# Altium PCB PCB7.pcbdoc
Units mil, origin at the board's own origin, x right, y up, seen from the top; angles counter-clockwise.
Board outline 2900 x 4300 mil, 2 copper layers (Top Layer, Bottom Layer); 31 components, 28 nets, 92 pads, 27 vias.
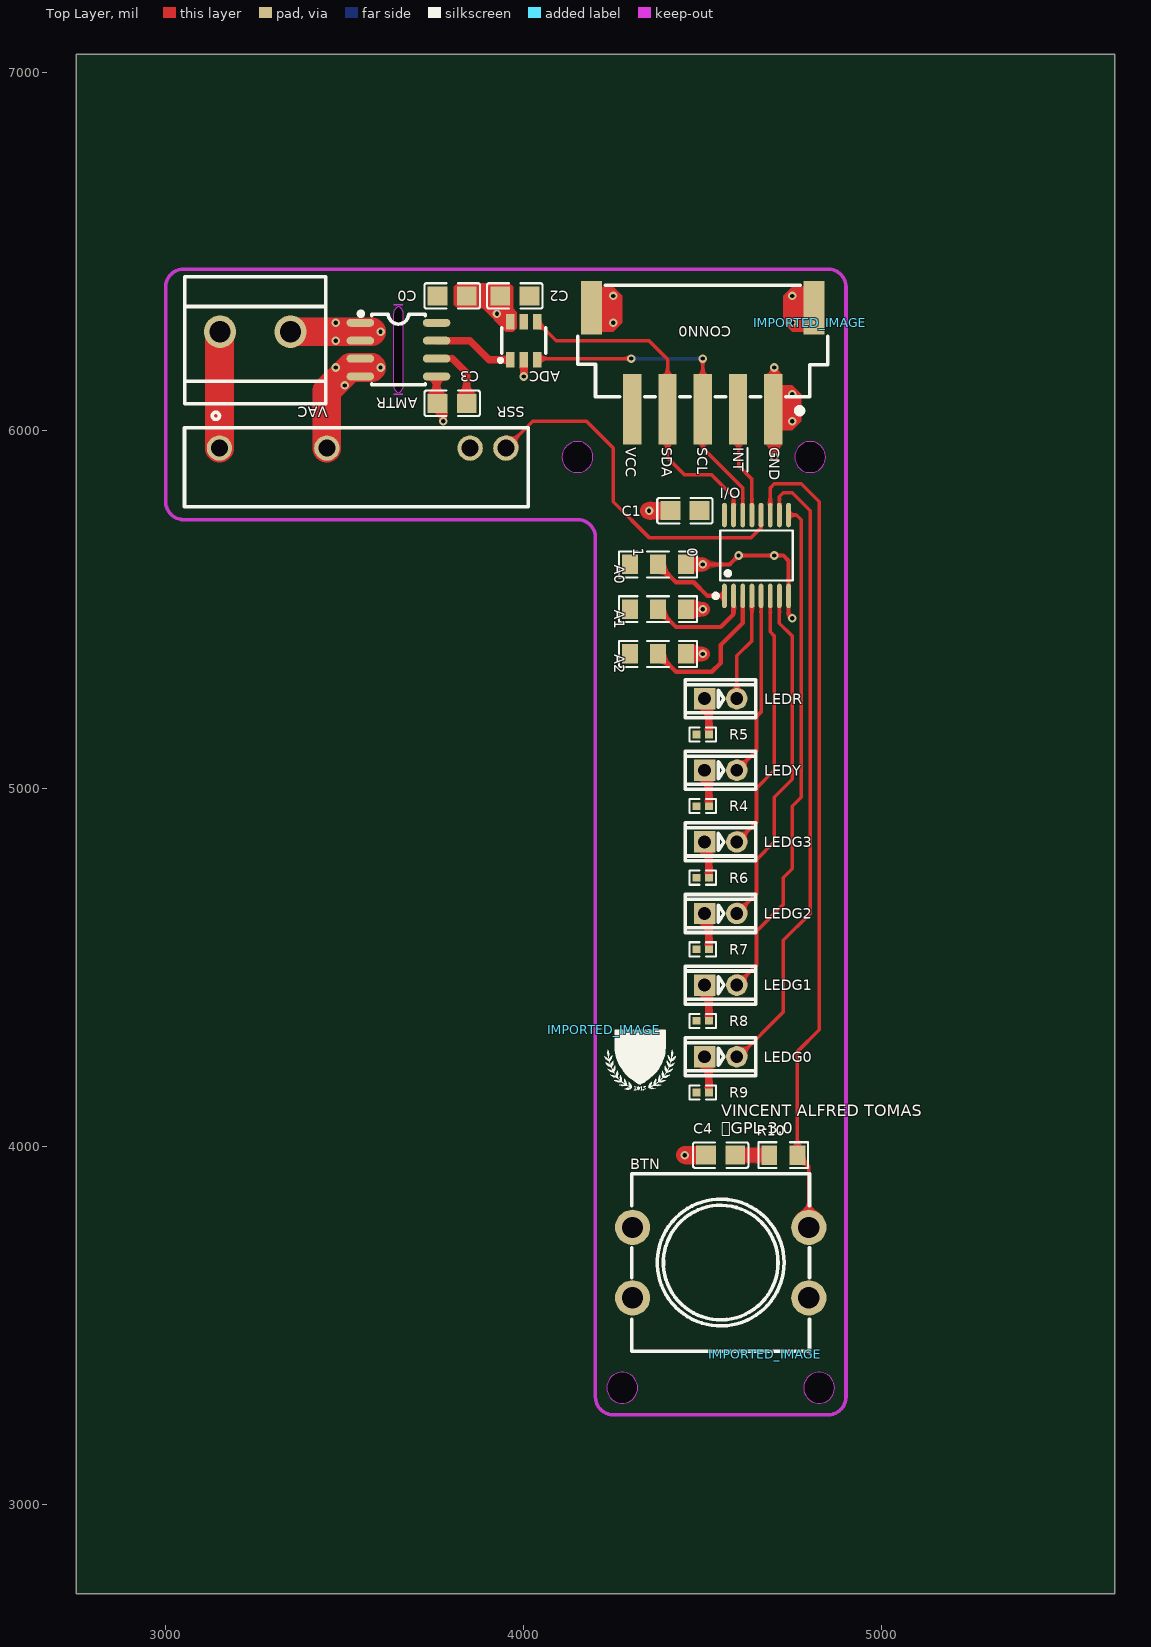
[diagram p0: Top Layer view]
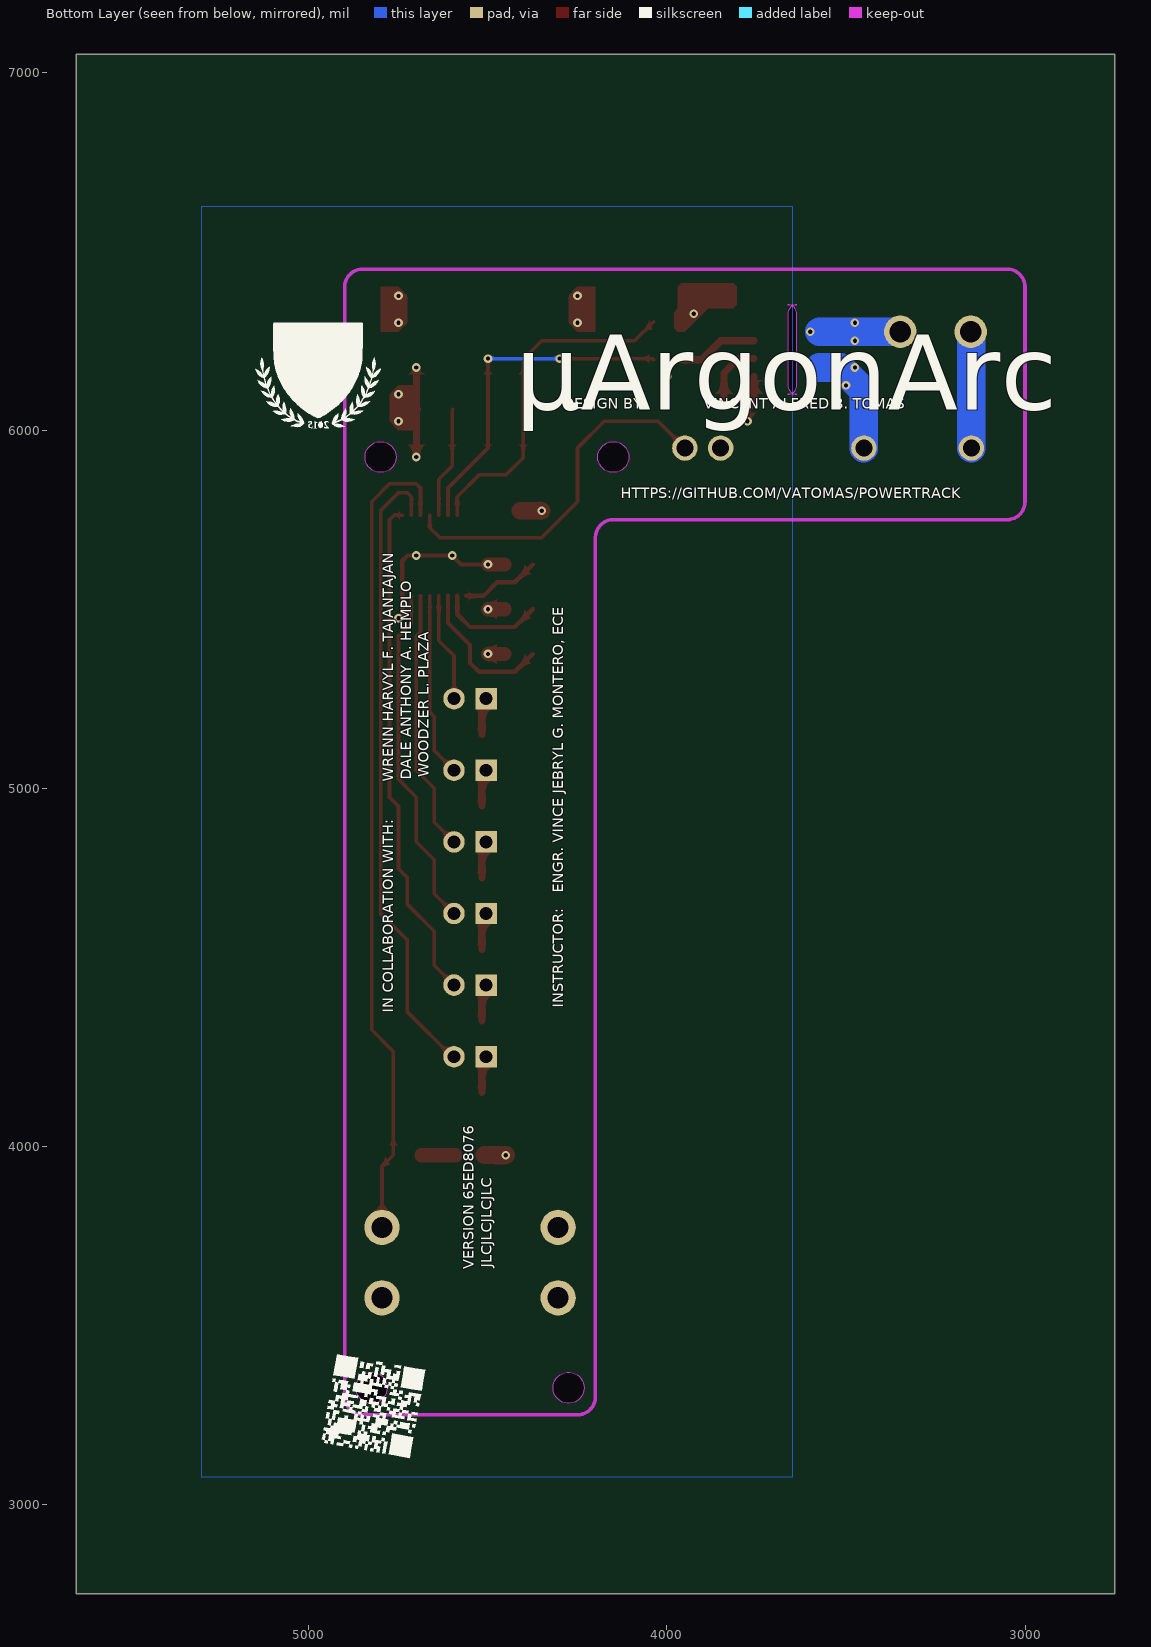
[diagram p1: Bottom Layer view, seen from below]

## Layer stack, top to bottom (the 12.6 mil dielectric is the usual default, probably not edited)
Top Layer: signal copper (thickness not stored)
Dielectric: dielectric 12.6, FR-4, Dk 4.8
Bottom Layer: signal copper (thickness not stored)

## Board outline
5650,2750 2750,2750 2750,7050 5650,7050
cut-out: 4843.31,5925 ccw(c4800,5925) 4756.69,5925 ccw(c4800,5925)
cut-out: 4193.31,5925 ccw(c4150,5925) 4106.69,5925 ccw(c4150,5925)
cut-out: 4868.31,3325 ccw(c4825,3325) 4781.69,3325 ccw(c4825,3325)
cut-out: 4318.31,3325 ccw(c4275,3325) 4231.69,3325 ccw(c4275,3325)
cut-out: 3662.5,6350 3637.5,6350 cw(c3637.5,6325) 3662.5,6325 3662.5,6125 cw(c3637.5,6125) 3637.5,6100 3662.5,6100 cw(c3662.5,6125) 3637.5,6125 3637.5,6325 cw(c3662.5,6325)

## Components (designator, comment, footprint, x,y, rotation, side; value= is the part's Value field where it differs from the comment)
A0 "Solder Switch" "Solder Switch" 4375,5625 r0 top
A1 "Solder Switch" "Solder Switch" 4375,5500 r0 top
A2 "Solder Switch" "Solder Switch" 4375,5375 r0 top
ADC "ADS1110A0IDBVR" SOT-23-6_L2.9-W1.6-P0.95-LS2.8-BR 4000,6250 r270 top
AMTR "ACS712ELCTR-05B-T" SOIC-8_L5.0-W4.0-P1.27-LS6.0-BL 3650,6225 r270 top
BTN "TS-1003-10026" SW-TH_4P-L12.0-W12.0-P5.00-LS12.5 4550,3675 r0 top
C0 "C2012X7T2E104KT000N" C0805 3800,6375 r180 top
C1 "C2012X7T2E104KT000N" C0805 4450,5775 r0 top
C2 "0805B181K500NT" C0805 3800,6075 r0 top
C3 "C2012X7T2E104KT000N" C0805 3975,6375 r0 top
C4 "0805B105K500NT_C215803" C0805 4550,3975 r180 top
CONN0 "XH-5PWB" CONN-SMD_5P-P2.50_DEALON_XH-5PWB 4500,6200 r180 top
I/O "TCA9534APWR" TSSOP-16_L5.0-W4.4-P0.65-LS6.4-BL 4650,5650 r0 top
IMPORTED_IMAGE "IMPORTED_IMAGE" IMPORTED_IMAGE 4225,4325 r0 top
IMPORTED_IMAGE "IMPORTED_IMAGE" IMPORTED_IMAGE 4675,3419.01 r0 top
IMPORTED_IMAGE "IMPORTED_IMAGE" IMPORTED_IMAGE 4800,6300 r0 top
LEDG0 "TZ-L2-25FYBYG2YCJ140-001" LED-TH_L5.0-W2.7-FD 4550,4250 r0 top
LEDG1 "TZ-L2-25FYBYG2YCJ140-001" LED-TH_L5.0-W2.7-FD 4550,4450 r0 top
LEDG2 "TZ-L2-25FYBYG2YCJ140-001" LED-TH_L5.0-W2.7-FD 4550,4650 r0 top
LEDG3 "TZ-L2-25FYBYG2YCJ140-001" LED-TH_L5.0-W2.7-FD 4550,4850 r0 top
LEDR "TJ-L257FGHRMFCSFLC2R-A5" LED-TH_L5.0-W2.7-FD 4550,5250 r0 top
LEDY "TZ-L2-25FYBY2YCJ150-001" LED-TH_L5.0-W2.7-FD 4550,5050 r0 top
R4 "CR0402FF2211G" R0402 4500,4950 r180 top
R5 "RTT023091FTH" R0402 4500,5150 r180 top
R6 "0402WGD3300TCE" R0402 4500,4750 r180 top
R7 "0402WGD3300TCE" R0402 4500,4550 r180 top
R8 "0402WGD3300TCE" R0402 4500,4350 r180 top
R9 "0402WGD3300TCE" R0402 4500,4150 r180 top
R10 "Res_0805" R0805 4725,3975 r0 top
SSR "G3MB-202PL" RELAY-TH_G3MB-202PL 3550,5950 r180 top
VAC "XY126V-5.0-2P" CONN-TH_XY126V-5.0-2P 3250,6275 r0 top

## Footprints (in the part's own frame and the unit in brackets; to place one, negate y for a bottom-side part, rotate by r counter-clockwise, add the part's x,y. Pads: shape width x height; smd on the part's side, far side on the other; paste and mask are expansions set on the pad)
C0805 [mm]
  rect 1.41x1.35 smd: 1(-1.03,0) 2(1.03,0)
  silkscreen extent -1.96,-0.9 1.96,0.9
CONN-SMD_5P-P2.50_DEALON_XH-5PWB [mm]
  rect 1.3x5 smd: 1(-5,3.6) 2(-2.5,3.6) 3(0,3.6) 4(2.5,3.6) 5(5,3.6)
  rect 1.5x3.8 smd: 6(-7.9,-3.6) 7(7.9,-3.6)
  silkscreen extent -8.86,-5.2 8.86,3.9
CONN-TH_XY126V-5.0-2P [mm]
  round 2.3 hole 1.5: 1(-2.5,0) 2(2.5,0)
  silkscreen extent -5,-5.1 5,3.9
IMPORTED_IMAGE [mil]
  silkscreen extent 0,-169 200,0
LED-TH_L5.0-W2.7-FD [mil]
  rect 60x60 hole 36: 1(-44.88,0)
  round 60 hole 36: 2(44.88,0)
  silkscreen extent -98,-53 98,53
R0402 [mm]
  rect 0.566x0.54 smd: 1(-0.433,0) 2(0.433,0)
  silkscreen extent -0.94,-0.5 0.94,0.5
R0805 [mm]
  rect 1.133x1.377 smd: 1(-1,0) 2(1,0)
  silkscreen extent -1.76,-0.92 1.76,0.92
RELAY-TH_G3MB-202PL [mm]
  round 1.8 hole 1.2: 1(10.16,0) 2(2.54,0) 3(-7.62,0) 4(-10.16,0)
  silkscreen extent -11.74,-2.54 12.64,4.15
SOIC-8_L5.0-W4.0-P1.27-LS6.0-BL [mil]
  oval 22.38x76.78 smd: 1(-75,-106.5) 2(-25,-106.5) 3(25,-106.5) 4(75,-106.5) 5(75,106.5) 6(25,106.5) 7(-25,106.5) 8(-75,106.5)
  silkscreen extent -106,-111 98,75
"Solder Switch" [mm]
  rect 1.133x1.377 smd: 1(-2,0) 2(0,0) 3(2,0)
  silkscreen extent -2.76,-0.92 2.76,0.92
SOT-23-6_L2.9-W1.6-P0.95-LS2.8-BR [mm]
  rect 1.1x0.6 smd: 1(1.35,-0.95) 2(1.35,0) 3(1.35,0.95) 4(-1.35,0.95) 5(-1.35,0) 6(-1.35,-0.95)
  silkscreen extent -0.9,-1.78 1.52,1.55
SW-TH_4P-L12.0-W12.0-P5.00-LS12.5 [mm]
  round 2.5 hole 1.5: 1(-6.25,2.5) 2(6.25,2.5) 3(-6.25,-2.5) 4(6.25,-2.5)
  silkscreen extent -6.3,-6.3 6.3,6.3
TSSOP-16_L5.0-W4.4-P0.65-LS6.4-BL [mil]
  oval 13.5x68.17 smd: 1(-89.57,-112.82) 2(-63.98,-112.82) 3(-38.39,-112.82) 4(-12.79,-112.82) 5(12.8,-112.82) 6(38.39,-112.82) 7(63.98,-112.82) 8(89.57,-112.82) 9(89.57,112.82) 10(63.98,112.82) 11(38.39,112.82) 12(12.8,112.82) 13(-12.79,112.82) 14(-38.39,112.82) 15(-63.98,112.82) 16(-89.57,112.82)
  silkscreen extent -120,-119 101,70

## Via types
v1: diameter 24.02, hole 12.01, Top Layer to Bottom Layer, 27 vias

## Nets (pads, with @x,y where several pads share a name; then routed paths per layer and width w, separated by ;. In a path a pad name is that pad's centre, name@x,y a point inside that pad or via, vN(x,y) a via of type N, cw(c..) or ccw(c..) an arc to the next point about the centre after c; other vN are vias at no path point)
$1N4404: LEDR.1 R5.1 | length 104.9
  Top Layer w20: LEDR.1 4517.04,5238.08 R5.1
$1N4407: LEDY.1 R4.1 | length 104.9
  Top Layer w20: LEDY.1 4517.04,5038.08 R4.1
$1N4410: LEDG3.1 R6.1 | length 104.9
  Top Layer w20: LEDG3.1 4517.04,4838.08 R6.1
$1N4413: LEDG2.1 R7.1 | length 104.9
  Top Layer w20: LEDG2.1 4517.04,4638.08 R7.1
$1N4416: LEDG1.1 R8.1 | length 104.9
  Top Layer w20: LEDG1.1 4517.04,4438.08 R8.1
$1N4419: LEDG0.1 R9.1 | length 104.9
  Top Layer w20: LEDG0.1 4517.04,4238.08 R9.1
$1N12131: AMTR.6 C2.2 | length 185.3
  Top Layer w20: AMTR.6 3800,6200 3840.55,6159.45 C2.2
$1N12380: ADC.1 AMTR.7 | length 228.1
  Top Layer w20: AMTR.7 3850,6250 3903.15,6196.85 ADC.1
$1N13268: AMTR.3 AMTR.4 SSR.2 | length 623.8
  Top Layer w80: SSR.2 3450,6110 3515,6175 3575,6175
  Bottom Layer w80: SSR.2 3450,6110 3515,6175 3575,6175
  other v1: 3500,6125 3475,6175 3600,6175
$1N13298: SSR.1 VAC.1 | length 651.3
  Top Layer w80: SSR.1 3150,6273.43 VAC.1
  Bottom Layer w80: SSR.1 3150,6273.43 VAC.1
$1N13302: AMTR.1 AMTR.2 VAC.2 | length 453.1
  Top Layer w80: VAC.2 3575,6275
  Bottom Layer w80: VAC.2 3575,6275
  other v1: 3475,6250 3600,6275 3475,6300
+5V: A0.1 A1.1 A2.1 ADC.5 AMTR.8 C0.2 C1.2 C3.2 C4.1 CONN0.5 I/O.16 R4.2 R5.2 R6.2 R7.2 R8.2 R9.2 R10.1 SSR.3 | length 95.1
  Top Layer w40: C4.1 R10.1
A0: A0.2 I/O.1 | length 221.8
  Top Layer w12: A0.2 4425,5575 4475,5575 4512.82,5537.18 I/O.1
A1: A1.2 I/O.2 | length 297.8
  Top Layer w12: A1.2 4425,5450 4550,5450 4586.02,5486.02 I/O.2
A2: A2.2 I/O.3 | length 418.8
  Top Layer w12: A2.2 4425,5325 4525,5325 4550,5350 4550,5400 4611.61,5461.61 I/O.3
BTN: BTN.2 I/O.11 R10.2 | length 2302.5
  Top Layer w10: I/O.11 4688.39,5838.39 4700,5850 4775,5850 4825,5800 4825,4325 4764.37,4264.37 R10.2 4796.06,3943.31 BTN.2
GND: A0.3 A1.3 A2.3 ADC.2 ADC.6 AMTR.5 BTN.3 BTN.4 C0.1 C1.1 C2.1 C3.1 C4.2 CONN0.1 CONN0.6 CONN0.7 I/O.8 | length 1110.5
  Top Layer w12: v1(4500,5625) 4575,5625 v1(4600,5650) v1(4700,5650) 4725,5650 4739.57,5635.43 I/O.8 4739.57,5485.43 v1(4750,5475)
  Top Layer w20: AMTR.5 3756.5,6077.95 C2.1 3775,6059.45 v1(3775,6025) ; v1(4000,6150) ADC.2 ; v1(4700,5925) 4700,6055.12 CONN0.1 4700,6061.42 v1(4700,6175)
  Top Layer w40: A2.3 v1(4500,5375) ; A1.3 v1(4500,5500) ; A0.3 v1(4500,5625)
  Top Layer w50: v1(4350,5775) C1.1 ; v1(4450,3975) C4.2
  other v1: 4750,6025 4750,6100 4250,6300 4750,6300 3925,6325 4250,6375 4750,6375
LED0: I/O.10 LEDG0.2 | length 1775.4
  Top Layer w10: LEDG0.2 4600,4250 4725,4375 4725,4575 4800,4650 4800,5775 4750,5825 4725,5825 4713.98,5813.98 I/O.10
LED1: I/O.9 LEDG1.2 | length 1415.4
  Top Layer w10: LEDG1.2 4650,4505.12 4650,4600 4725,4675 4725,4750 4750,4775 4750,4950 4775,4975 4775,5750 4762.18,5762.82 I/O.9
LED2: I/O.7 LEDG2.2 | length 966.3
  Top Layer w10: LEDG2.2 4650,4705.12 4650,4800 4700,4850 4700,4975 4750,5025 4750,5425 4713.98,5461.02 I/O.7
LED3: I/O.6 LEDG3.2 | length 735.5
  Top Layer w10: LEDG3.2 4650,4905.12 4650,5000 4700,5050 4700,5425 4688.39,5436.61 I/O.6
LED4: I/O.5 LEDY.2 | length 515.3
  Top Layer w10: LEDY.2 4650,5105.12 4650,5200 4662.8,5212.8 I/O.5
LED5: I/O.4 LEDR.2 | length 304.7
  Top Layer w10: LEDR.2 4594.88,5369.88 4637.21,5412.21 I/O.4
SCL: ADC.3 CONN0.3 I/O.14 | length 947.3
  Top Layer w10: ADC.3 4040.55,6200 v1(4300,6200) ; v1(4500,6200) CONN0.3 4500,5950 4611.61,5838.39 I/O.14
  Bottom Layer w10: v1(4300,6200) v1(4500,6200)
SDA: ADC.4 CONN0.4 I/O.15 | length 963.5
  Top Layer w10: ADC.4 4090.55,6250 4350,6250 4401.57,6198.43 CONN0.4 4401.57,5923.43 4450,5875 4525,5875 4586.02,5813.98 I/O.15
SSR: I/O.12 SSR.4 | length 1012.9
  Top Layer w10: SSR.4 4025,6025 4175,6025 4250,5950 4250,5800 4350,5700 4635.06,5700 4662.8,5727.74 I/O.12
~INT: CONN0.2 I/O.13 | length 311.5
  Top Layer w10: CONN0.2 4600,6056.7 4600,5900 4637.21,5862.79 I/O.13
"": BTN.1

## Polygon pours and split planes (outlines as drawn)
GND on Bottom Layer (solid, remove dead copper, pour order 0): 3650,3075 5300,3075 5300,6625 3650,6625
+5V on Top Layer (solid, remove dead copper, pour order 2): 3675,3000 5400,3000 5400,6800 3675,6800
GND on Top Layer (solid, remove dead copper, pour order 1): 4450,5575 4475,5575 4512.82,5537.18 4560.43,5537.18 4775,5534.31 4775,5750 4762.18,5762.82 4586.02,5762.82 4587.62,5700 4450,5700

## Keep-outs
Board Outline Layer:
  lines w10 net "": 3000,5800 ccw(c3050,5800) 3050,5750 4150,5750 cw(c4150,5700) 4199.99,5700.72 4199.99,3300 ccw(c4249.99,3300) 4249.99,3250 4850,3250 ccw(c4850,3300) 4900,3300 4900,6400 ccw(c4850,6400) 4850,6450 3050,6450 ccw(c3050,6400) 3000,6400 3000,5800
Multi-Layer:
  region net "": 4843.31,5925 ccw(c4800,5925) 4756.69,5925 ccw(c4800,5925)
  region net "": 4193.31,5925 ccw(c4150,5925) 4106.69,5925 ccw(c4150,5925)
  region net "": 4868.31,3325 ccw(c4825,3325) 4781.69,3325 ccw(c4825,3325)
  region net "": 4318.31,3325 ccw(c4275,3325) 4231.69,3325 ccw(c4275,3325)
  region net "": 3662.5,6350 3637.5,6350 cw(c3637.5,6325) 3662.5,6325 3662.5,6125 cw(c3637.5,6125) 3637.5,6100 3662.5,6100 cw(c3662.5,6125) 3637.5,6125 3637.5,6325 cw(c3662.5,6325)

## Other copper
Top Layer:
  region net GND: 3815,6410 3960,6410 3970,6400 3970,6340 3980,6330 3980,6285 3970,6275 3950,6275 3885,6340 3815,6340 3805,6350 3805,6400
  region net GND: 4200,6400 4200,6275 4250,6275 4275,6300 4275,6375 4250,6400
  region net GND: 4800,6275 4800,6400 4750,6400 4725,6375 4725,6300 4750,6275
  region net GND: 4700,6125 4700,6000 4750,6000 4775,6025 4775,6100 4750,6125
  region net A0: 4535.68,5543.18 4535.68,5531.18 4541.49,5531.08 4543.84,5530.9 4545.33,5530.7 4546.74,5530.42 4548.05,5530.05 4548.67,5529.83 4549.26,5529.57 4549.83,5529.29 4550.36,5528.98 4550.85,5528.63 4551.32,5528.25 4551.74,5527.83 4552.13,5527.38 4552.48,5526.88 4552.79,5526.35 4553.05,5525.77 4553.27,5525.15 4553.45,5524.48 4553.57,5523.76 4553.65,5522.99 4553.68,5522.18 4553.68,5552.18 4553.65,5551.36 4553.57,5550.59 4553.45,5549.87 4553.27,5549.2 4553.05,5548.58 4552.79,5548 4552.48,5547.47 4552.13,5546.97 4551.74,5546.52 4551.32,5546.1 4550.85,5545.72 4550.36,5545.37 4549.83,5545.06 4549.26,5544.78 4548.67,5544.52 4548.05,5544.3 4546.74,5543.93 4545.33,5543.65 4543.84,5543.45 4541.49,5543.27
  region net A1: 4580.02,5488.75 4592.02,5488.75 4592.77,5509.84 4579.27,5509.84
  region net A2: 4605.61,5488.75 4617.61,5488.75 4617.54,5489.59 4617.36,5490.52 4616.72,5492.61 4615.02,5497.17 4614.33,5499.37 4614.11,5500.4 4614,5501.35 4614.02,5502.21 4614.2,5502.96 4614.56,5503.59 4615.13,5504.08 4608.09,5504.08 4608.66,5503.59 4609.02,5502.96 4609.2,5502.21 4609.22,5501.35 4609.11,5500.4 4608.89,5499.37 4608.2,5497.17 4606.5,5492.61 4605.86,5490.52 4605.68,5489.59
  region net LED5: 4632.21,5490.3 4642.21,5490.3 4643.89,5508.76 4643.96,5509.84 4630.46,5509.84 4632.13,5491.39
  region net LED4: 4657.8,5490.3 4667.8,5490.3 4667.75,5492.22 4667.52,5495.02 4667.16,5498.4 4667.1,5499.77 4667.12,5500.68 4667.2,5501.6 4667.34,5502.56 4667.57,5503.54 4667.89,5504.58 4668.32,5505.68 4668.85,5506.85 4656.75,5506.85 4657.28,5505.68 4657.71,5504.58 4658.03,5503.54 4658.26,5502.56 4658.4,5501.6 4658.48,5500.68 4658.5,5499.77 4658.44,5498.4 4657.98,5493.95 4657.82,5491.61
  region net LED3: 4683.39,5490.3 4693.39,5490.3 4693.34,5492.22 4693.11,5495.02 4692.75,5498.4 4692.69,5499.77 4692.71,5500.68 4692.79,5501.6 4692.93,5502.56 4693.16,5503.54 4693.48,5504.58 4693.91,5505.68 4694.44,5506.85 4682.34,5506.85 4682.87,5505.68 4683.3,5504.58 4683.62,5503.54 4683.85,5502.56 4683.99,5501.6 4684.07,5500.68 4684.09,5499.77 4684.03,5498.4 4683.57,5493.95 4683.41,5491.61
  region net LED2: 4708.98,5490.3 4718.98,5490.3 4718.93,5492.22 4718.7,5495.02 4718.34,5498.4 4718.28,5499.77 4718.3,5500.68 4718.38,5501.6 4718.52,5502.56 4718.75,5503.54 4719.07,5504.58 4719.5,5505.68 4720.03,5506.85 4707.93,5506.85 4708.46,5505.68 4708.89,5504.58 4709.21,5503.54 4709.44,5502.56 4709.58,5501.6 4709.66,5500.68 4709.68,5499.77 4709.62,5498.4 4709.16,5493.95 4709,5491.61
  region net GND: 4733.57,5488.75 4745.57,5488.75 4745.5,5489.59 4745.32,5490.52 4744.68,5492.61 4742.98,5497.17 4742.29,5499.37 4742.07,5500.4 4741.96,5501.35 4741.98,5502.21 4742.16,5502.96 4742.52,5503.59 4743.09,5504.08 4736.05,5504.08 4736.62,5503.59 4736.98,5502.96 4737.16,5502.21 4737.18,5501.35 4737.07,5500.4 4736.85,5499.37 4736.16,5497.17 4734.46,5492.61 4733.82,5490.52 4733.64,5489.59
  region net SDA: 4591.02,5809.7 4581.02,5809.7 4579.34,5791.24 4579.27,5790.16 4592.77,5790.16 4591.1,5808.61
  region net SCL: 4616.61,5809.7 4606.61,5809.7 4606.66,5807.78 4606.89,5804.98 4607.25,5801.6 4607.31,5800.23 4607.29,5799.32 4607.21,5798.4 4607.07,5797.44 4606.84,5796.46 4606.52,5795.42 4606.09,5794.32 4605.56,5793.15 4617.66,5793.15 4617.13,5794.32 4616.7,5795.42 4616.38,5796.46 4616.15,5797.44 4616.01,5798.4 4615.93,5799.32 4615.91,5800.23 4615.97,5801.6 4616.43,5806.05 4616.59,5808.39
  region net ~INT: 4642.21,5809.7 4632.21,5809.7 4632.26,5807.78 4632.49,5804.98 4632.85,5801.6 4632.91,5800.23 4632.89,5799.32 4632.81,5798.4 4632.67,5797.44 4632.44,5796.46 4632.12,5795.42 4631.69,5794.32 4631.16,5793.15 4643.26,5793.15 4642.73,5794.32 4642.3,5795.42 4641.98,5796.46 4641.75,5797.44 4641.61,5798.4 4641.53,5799.32 4641.51,5800.23 4641.57,5801.6 4642.03,5806.05 4642.19,5808.39
  region net SSR: 4657.8,5727.74 4667.8,5727.74 4667.88,5728.32 4669.28,5734 4669.48,5734.91 4669.55,5735.49 4656.05,5735.49 4656.12,5734.91 4657.53,5729.23 4657.72,5728.32
  region net BTN: 4693.39,5809.7 4683.39,5809.7 4681.71,5791.24 4681.64,5790.16 4695.14,5790.16 4693.47,5808.61
  region net LED0: 4718.98,5809.7 4708.98,5809.7 4709.03,5807.78 4709.26,5804.98 4709.62,5801.6 4709.68,5800.23 4709.66,5799.32 4709.58,5798.4 4709.44,5797.44 4709.21,5796.46 4708.89,5795.42 4708.46,5794.32 4707.93,5793.15 4720.03,5793.15 4719.5,5794.32 4719.07,5795.42 4718.75,5796.46 4718.52,5797.44 4718.38,5798.4 4718.3,5799.32 4718.28,5800.23 4718.34,5801.6 4718.8,5806.05 4718.96,5808.39
  region net LED1: 4761.32,5757.82 4761.32,5767.82 4756.48,5767.9 4754.52,5768.05 4753.28,5768.22 4752.11,5768.45 4751.01,5768.76 4750.49,5768.95 4750,5769.16 4749.53,5769.39 4749.09,5769.66 4748.68,5769.94 4748.29,5770.26 4747.93,5770.61 4747.61,5770.99 4747.32,5771.4 4747.06,5771.85 4746.84,5772.33 4746.66,5772.85 4746.51,5773.41 4746.41,5774 4746.34,5774.64 4746.32,5775.32 4746.32,5750.32 4746.34,5751.01 4746.41,5751.65 4746.51,5752.24 4746.66,5752.8 4746.84,5753.32 4747.06,5753.8 4747.32,5754.25 4747.61,5754.66 4747.93,5755.04 4748.29,5755.39 4748.68,5755.71 4749.09,5755.99 4749.53,5756.26 4750,5756.49 4750.49,5756.7 4751.01,5756.89 4752.11,5757.2 4753.28,5757.43 4754.52,5757.6 4756.48,5757.75
  region net BTN: 4801.06,3840.42 4791.06,3840.42 4791.04,3839.86 4790.99,3839.29 4790.91,3838.72 4790.79,3838.15 4790.46,3837 4790.02,3835.85 4789.46,3834.7 4788.8,3833.54 4788.04,3832.38 4786.74,3830.65 4785.27,3828.91 4783.07,3826.61 4779.39,3823.19 4768.14,3813.99 4762.81,3809.56 4760.82,3807.72 4759.54,3806.4 4759.15,3805.98 4832.97,3805.98 4831.75,3807.28 4829.83,3809.09 4824.62,3813.48 4813.37,3822.63 4809.64,3826.04 4807.38,3828.34 4805.85,3830.07 4804.49,3831.81 4803.69,3832.96 4802.98,3834.12 4802.37,3835.28 4801.87,3836.43 4801.48,3837.58 4801.33,3838.15 4801.21,3838.72 4801.13,3839.29 4801.08,3839.86
  region net SSR: 3987.65,5980.58 3980.58,5987.65 3978.99,5986.16 3977.98,5985.33 3977,5984.6 3976.05,5983.98 3975.12,5983.46 3974.21,5983.04 3973.32,5982.7 3972.44,5982.45 3971.57,5982.27 3970.71,5982.17 3969.85,5982.12 3968.99,5982.14 3968.14,5982.21 3966.84,5982.39 3965.06,5982.76 3959.76,5984.15 3957.03,5984.76 3954.65,5985.14 3952.74,5985.34 3950.7,5985.43 3948.54,5985.4 3947.78,5985.36 3985.36,5947.78 3985.44,5950 3985.38,5952.08 3985.22,5954.03 3984.87,5956.45 3984.28,5959.23 3982.88,5964.61 3982.47,5966.4 3982.26,5967.7 3982.17,5968.57 3982.13,5969.42 3982.14,5970.28 3982.21,5971.14 3982.35,5972 3982.57,5972.87 3982.86,5973.76 3983.24,5974.66 3983.71,5975.58 3984.28,5976.52 3984.95,5977.49 3985.73,5978.49 3987.12,5980.04
  region net $1N12380: 3818.72,6240 3818.72,6260 3783.7,6261.19 3783.7,6238.81
  region net $1N12131: 3800,6190 3800,6210 3799.09,6209.74 3798.13,6209.07 3796.2,6207.19 3795.3,6206.3 3794.48,6205.67 3793.78,6205.47 3793.23,6205.86 3793.23,6194.14 3793.78,6194.53 3794.48,6194.33 3795.3,6193.7 3797.16,6191.83 3798.13,6190.93 3799.09,6190.26
  region net GND: 3746.5,6108.81 3766.5,6108.81 3766.66,6118.5 3766.96,6122.42 3767.29,6124.9 3767.63,6126.67 3768.05,6128.36 3768.56,6129.96 3768.95,6130.97 3769.4,6131.93 3769.89,6132.84 3770.44,6133.7 3771.05,6134.5 3771.71,6135.24 3772.44,6135.92 3773.23,6136.53 3774.09,6137.08 3775.02,6137.56 3776.02,6137.96 3777.1,6138.29 3778.25,6138.54 3779.49,6138.71 3780.81,6138.8 3781.5,6138.81 3731.5,6138.81 3732.86,6138.77 3734.14,6138.64 3735.34,6138.43 3736.45,6138.14 3737.49,6137.77 3738.45,6137.33 3739.35,6136.81 3740.17,6136.23 3740.93,6135.59 3741.63,6134.87 3742.26,6134.1 3742.84,6133.27 3743.36,6132.39 3743.83,6131.45 3744.25,6130.47 3744.62,6129.44 3745.1,6127.81 3745.49,6126.09 3745.89,6123.67 3746.22,6120.48 3746.46,6115.1
  region net SCL: 4064.21,6195 4064.21,6205 cw(c4064.21,6223.75) 4049.21,6212.5 4049.21,6187.5 cw(c4064.21,6176.25)
  region net GND: 3990,6150 4010,6150 cw(c4195.55,6150) 4011.72,6175.2 3988.28,6175.2 cw(c3804.45,6150)
  region net $1N12380: 3920.79,6206.85 3920.79,6186.85 cw(c3920.79,5972.46) 3950.79,6184.74 3950.79,6208.96 cw(c3920.79,6421.24)
  region net SDA: 4059.82,6273.66 4059.82,6287.8 cw(c4086.33,6314.32) 4049.21,6309.02 4041.38,6281.5 cw(c4040.89,6254.73)
  region net $1N4419: 4507.04,4190 4527.04,4190 cw(c4741.43,4190) 4529.15,4220 4492.04,4220 cw(c4469.54,4190)
  region net LED0: 4629.86,4272.78 4622.78,4279.86 4622.23,4279.36 4621.61,4278.93 4620.94,4278.57 4620.21,4278.26 4619.44,4278.01 4618.62,4277.81 4617.77,4277.66 4615.94,4277.5 4613.99,4277.49 4610.9,4277.71 4605.52,4278.47 4597.27,4279.75 4595.44,4279.92 4593.77,4279.97 4593,4279.94 4624.82,4248.12 4624.92,4250.97 4624.76,4257.79 4624.77,4260.86 4624.86,4262.33 4625.04,4263.77 4625.34,4265.19 4625.76,4266.58 4626.03,4267.27 4626.34,4267.96 4626.69,4268.65 4627.09,4269.34 4628.03,4270.71 4629.19,4272.09
  region net $1N4407: 4507.04,4990 4527.04,4990 cw(c4741.43,4990) 4529.15,5020 4492.04,5020 cw(c4469.54,4990)
  region net LED4: 4627.3,5075.34 4620.22,5082.42 4618.94,5081.21 4618.11,5080.52 4617.31,5079.93 4616.52,5079.41 4615.75,5078.97 4614.99,5078.61 4614.25,5078.32 4613.52,5078.09 4612.79,5077.93 4612.06,5077.81 4611.34,5077.75 4610.62,5077.74 4609.9,5077.77 4608.8,5077.87 4607.3,5078.12 4602.41,5079.18 4600.1,5079.6 4598.1,5079.86 4596.5,5079.97 4594.8,5080 4593,5079.94 4624.82,5048.12 4624.88,5049.92 4624.85,5051.62 4624.68,5053.74 4624.41,5055.7 4623.78,5058.83 4622.93,5062.8 4622.75,5063.92 4622.65,5065.02 4622.62,5065.74 4622.63,5066.46 4622.69,5067.18 4622.81,5067.91 4622.97,5068.64 4623.2,5069.37 4623.49,5070.11 4623.85,5070.87 4624.29,5071.64 4624.81,5072.43 4625.4,5073.23 4626.09,5074.06
  region net $1N4404: 4507.04,5190 4527.04,5190 cw(c4741.43,5190) 4529.15,5220 4492.04,5220 cw(c4469.54,5190)
  region net LED5: 4599.88,5290.84 4589.88,5290.84 4589.82,5289.08 4589.72,5288.01 4589.58,5287.02 4589.39,5286.1 4589.15,5285.25 4588.87,5284.46 4588.55,5283.72 4588.19,5283.04 4587.8,5282.41 4587.36,5281.82 4586.9,5281.27 4586.4,5280.74 4585.87,5280.25 4585.01,5279.55 4583.78,5278.67 4579.57,5275.96 4577.64,5274.62 4576.05,5273.39 4574.83,5272.34 4573.61,5271.16 4572.38,5269.84 4617.38,5269.84 4616.15,5271.16 4614.93,5272.34 4613.31,5273.71 4611.73,5274.91 4609.08,5276.68 4605.66,5278.88 4604.75,5279.55 4603.89,5280.25 4603.36,5280.74 4602.86,5281.27 4602.4,5281.82 4601.96,5282.41 4601.57,5283.04 4601.21,5283.72 4600.89,5284.46 4600.61,5285.25 4600.37,5286.1 4600.18,5287.02 4600.04,5288.01 4599.94,5289.08
  region net $1N4416: 4507.04,4390 4527.04,4390 cw(c4741.43,4390) 4529.15,4420 4492.04,4420 cw(c4469.54,4390)
  region net LED1: 4627.3,4475.34 4620.22,4482.42 4618.94,4481.21 4618.11,4480.52 4617.31,4479.93 4616.52,4479.41 4615.75,4478.97 4614.99,4478.61 4614.25,4478.32 4613.52,4478.09 4612.79,4477.93 4612.06,4477.81 4611.34,4477.75 4610.62,4477.74 4609.9,4477.77 4608.8,4477.87 4607.3,4478.12 4602.41,4479.18 4600.1,4479.6 4598.1,4479.86 4596.5,4479.97 4594.8,4480 4593,4479.94 4624.82,4448.12 4624.88,4449.92 4624.85,4451.62 4624.68,4453.74 4624.41,4455.7 4623.78,4458.83 4622.93,4462.8 4622.75,4463.92 4622.65,4465.02 4622.62,4465.74 4622.63,4466.46 4622.69,4467.18 4622.81,4467.91 4622.97,4468.64 4623.2,4469.37 4623.49,4470.11 4623.85,4470.87 4624.29,4471.64 4624.81,4472.43 4625.4,4473.23 4626.09,4474.06
  region net $1N4413: 4507.04,4590 4527.04,4590 cw(c4741.43,4590) 4529.15,4620 4492.04,4620 cw(c4469.54,4590)
  region net LED2: 4627.3,4675.34 4620.22,4682.42 4618.94,4681.21 4618.11,4680.52 4617.31,4679.93 4616.52,4679.41 4615.75,4678.97 4614.99,4678.61 4614.25,4678.32 4613.52,4678.09 4612.79,4677.93 4612.06,4677.81 4611.34,4677.75 4610.62,4677.74 4609.9,4677.77 4608.8,4677.87 4607.3,4678.12 4602.41,4679.18 4600.1,4679.6 4598.1,4679.86 4596.5,4679.97 4594.8,4680 4593,4679.94 4624.82,4648.12 4624.88,4649.92 4624.85,4651.62 4624.68,4653.74 4624.41,4655.7 4623.78,4658.83 4622.93,4662.8 4622.75,4663.92 4622.65,4665.02 4622.62,4665.74 4622.63,4666.46 4622.69,4667.18 4622.81,4667.91 4622.97,4668.64 4623.2,4669.37 4623.49,4670.11 4623.85,4670.87 4624.29,4671.64 4624.81,4672.43 4625.4,4673.23 4626.09,4674.06
  region net $1N4410: 4507.04,4790 4527.04,4790 cw(c4741.43,4790) 4529.15,4820 4492.04,4820 cw(c4469.54,4790)
  region net LED3: 4627.3,4875.34 4620.22,4882.42 4618.94,4881.21 4618.11,4880.52 4617.31,4879.93 4616.52,4879.41 4615.75,4878.97 4614.99,4878.61 4614.25,4878.32 4613.52,4878.09 4612.79,4877.93 4612.06,4877.81 4611.34,4877.75 4610.62,4877.74 4609.9,4877.77 4608.8,4877.87 4607.3,4878.12 4602.41,4879.18 4600.1,4879.6 4598.1,4879.86 4596.5,4879.97 4594.8,4880 4593,4879.94 4624.82,4848.12 4624.88,4849.92 4624.85,4851.62 4624.68,4853.74 4624.41,4855.7 4623.78,4858.83 4622.93,4862.8 4622.75,4863.92 4622.65,4865.02 4622.62,4865.74 4622.63,4866.46 4622.69,4867.18 4622.81,4867.91 4622.97,4868.64 4623.2,4869.37 4623.49,4870.11 4623.85,4870.87 4624.29,4871.64 4624.81,4872.43 4625.4,4873.23 4626.09,4874.06
  region net $1N4407: 4527.04,4990.63 4507.04,4990.63 cw(c4110,4990.63) 4505.9,4960.63 4528.18,4960.63 cw(c4924.08,4990.63)
  region net $1N4410: 4527.04,4790.63 4507.04,4790.63 cw(c4110,4790.63) 4505.9,4760.63 4528.18,4760.63 cw(c4924.08,4790.63)
  region net $1N4404: 4527.04,5190.63 4507.04,5190.63 cw(c4110,5190.63) 4505.9,5160.63 4528.18,5160.63 cw(c4924.08,5190.63)
  region net $1N4413: 4527.04,4590.63 4507.04,4590.63 cw(c4110,4590.63) 4505.9,4560.63 4528.18,4560.63 cw(c4924.08,4590.63)
  region net $1N4416: 4527.04,4390.63 4507.04,4390.63 cw(c4110,4390.63) 4505.9,4360.63 4528.18,4360.63 cw(c4924.08,4390.63)
  region net $1N4419: 4527.04,4190.63 4507.04,4190.63 cw(c4110,4190.63) 4505.9,4160.63 4528.18,4160.63 cw(c4924.08,4190.63)
  region net GND: 4450,4000 4450,3950 cw(c4450,3630.32) 4481.69,3948.43 4481.69,4001.57 cw(c4450,4319.68)
  region net GND: 4350,5800 4350,5750 ccw(c4350,5803.7) 4381.69,5760.35 4381.69,5789.65 ccw(c4350,5746.3)
  region net $1N12131: 3850.55,6131.57 3830.55,6131.57 cw(c3793.05,6131.57) 3815.55,6101.57 3865.55,6101.57 cw(c3888.05,6131.57)
  region net GND: 3766.5,6131.57 3746.5,6131.57 cw(c3708.7,6131.57) 3731.69,6101.57 3781.5,6101.57 cw(c3804,6131.57)
  region net GND: 3765,6025 3785,6025 cw(c3916.12,6025) 3787.11,6048.43 3750,6048.43 cw(c3739.21,6025)
  region net GND: 4690,5929.85 4710,5929.85 cw(c4752.39,5929.85) 4722.44,5959.85 4675,5959.85 cw(c4652.5,5929.85)
  region net GND: 4710,6175 4690,6175 cw(c4671.33,6175) 4675,6156.69 4722.44,6156.69 cw(c4729.69,6175)
  region net ~INT: 4595,5944.85 4605,5944.85 cw(c4623.75,5944.85) 4612.5,5959.85 4587.5,5959.85 cw(c4576.25,5944.85)
  region net SCL: 4495,5950 4505,5950 cw(c4515.21,5950) 4512.5,5959.85 4487.5,5959.85 cw(c4484.79,5950)
  region net SCL: 4505,6171.69 4495,6171.69 cw(c4476.25,6171.69) 4487.5,6156.69 4512.5,6156.69 cw(c4523.75,6171.69)
  region net SDA: 4396.57,5944.85 4406.57,5944.85 cw(c4425.32,5944.85) 4414.07,5959.85 4389.07,5959.85 cw(c4377.82,5944.85)
  region net SDA: 4406.57,6171.69 4396.57,6171.69 cw(c4377.82,6171.69) 4389.07,6156.69 4414.07,6156.69 cw(c4425.32,6171.69)
  region net A0: 4406.35,5585.17 4410.02,5598.46 cw(c4441.84,5630.28) 4397.29,5623.92 4380.89,5597.89 cw(c4374.53,5553.35)
  region net A1: 4406.35,5460.17 4410.02,5473.46 cw(c4441.84,5505.28) 4397.29,5498.92 4380.89,5472.89 cw(c4374.53,5428.35)
  region net GND: 4500,5480 4500,5520 cw(c4500,5563.96) 4476.03,5527.11 4476.03,5472.89 cw(c4500,5436.04)
  region net A2: 4406.35,5335.17 4410.02,5348.46 cw(c4441.84,5380.28) 4397.29,5373.92 4380.89,5347.89 cw(c4374.53,5303.35)
  region net GND: 4500,5355 4500,5395 cw(c4500,5438.96) 4476.03,5402.11 4476.03,5347.89 cw(c4500,5311.04)
  region net BTN: 4769.37,4017.11 4759.37,4017.11 cw(c4740.62,4017.11) 4751.87,4002.11 4776.87,4002.11 cw(c4788.12,4017.11)
  region net BTN: 4792.52,3939.77 4797.27,3949.17 cw(c4823.79,3975.69) 4786.66,3970.38 4773.8,3947.89 cw(c4772.89,3920.14)
  region net GND: 4743.81,5489.67 4735.33,5481.19 4735.9,5480.52 4736.41,5479.74 4736.85,5478.88 4737.22,5477.97 4737.53,5477.02 4737.76,5476.06 4737.93,5475.13 4738.02,5474.25 4750.75,5486.98 4749.87,5487.07 4748.94,5487.24 4747.98,5487.47 4747.03,5487.78 4746.12,5488.15 4745.26,5488.59 4744.48,5489.1
  region net SCL: 4283.65,6205 4283.65,6195 4284.22,6194.98 4284.79,6194.91 4285.36,6194.8 4285.92,6194.66 4286.49,6194.47 4287.59,6194.02 4288.67,6193.46 4289.71,6192.81 4290.7,6192.11 4292.06,6190.99 4292.06,6209.01 4290.7,6207.89 4289.71,6207.19 4288.67,6206.54 4287.59,6205.98 4286.49,6205.53 4285.92,6205.34 4285.36,6205.2 4284.79,6205.09 4284.22,6205.02
  region net SCL: 4495,6183.65 4505,6183.65 4505.02,6184.22 4505.09,6184.79 4505.2,6185.36 4505.34,6185.92 4505.53,6186.49 4505.98,6187.59 4506.54,6188.67 4507.19,6189.71 4507.89,6190.7 4509.01,6192.06 4490.99,6192.06 4492.11,6190.7 4492.81,6189.71 4493.46,6188.67 4494.02,6187.59 4494.47,6186.49 4494.66,6185.92 4494.8,6185.36 4494.91,6184.79 4494.98,6184.22
Bottom Layer:
  region net SCL: 4316.35,6195 4316.35,6205 4315.78,6205.02 4315.21,6205.09 4314.64,6205.2 4314.08,6205.34 4313.51,6205.53 4312.41,6205.98 4311.33,6206.54 4310.29,6207.19 4309.3,6207.89 4307.94,6209.01 4307.94,6190.99 4309.3,6192.11 4310.29,6192.81 4311.33,6193.46 4312.41,6194.02 4313.51,6194.47 4314.08,6194.66 4314.64,6194.8 4315.21,6194.91 4315.78,6194.98
  region net SCL: 4483.65,6205 4483.65,6195 4484.22,6194.98 4484.79,6194.91 4485.36,6194.8 4485.92,6194.66 4486.49,6194.47 4487.59,6194.02 4488.67,6193.46 4489.71,6192.81 4490.7,6192.11 4492.06,6190.99 4492.06,6209.01 4490.7,6207.89 4489.71,6207.19 4488.67,6206.54 4487.59,6205.98 4486.49,6205.53 4485.92,6205.34 4485.36,6205.2 4484.79,6205.09 4484.22,6205.02

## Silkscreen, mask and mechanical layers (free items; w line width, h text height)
Top Silkscreen Layer:
  lines w6 net "": 4625,5885 4625,5950
  text "VCC" at 4285.05,5952.51 h29.38 r270
  text "SDA" at 4385.05,5952.51 h29.38 r270
  text "SCL" at 4485.05,5952.51 h29.38 r270
  text "INT" at 4585.05,5952.51 h29.38 r270
  text "GND" at 4685.05,5952.51 h29.38 r270
  text "1" at 4306.35,5672.21 h29.6 r270
  text "0" at 4456.35,5672.21 h29.6 r270
  text "VINCENT ALFRED TOMAS /  GPL-3.0" at 4551.92,4035.06 h32.78
Bottom Silkscreen Layer:
  text "VINCENT ALFRED B. TOMAS" at 3896.67,6060.06 h29.4
  text "DESIGN BY" at 4289.74,6060.06 h29.4
  text "µArgonArc" at 4423.93,6056.64 h210
  text "HTTPS://GITHUB.COM/VATOMAS/POWERTRACK" at 4128.59,5810.06 h29.4
  text "WOODZER L. PLAZA" at 4664.94,5030.71 h29.4 r270
  text "DALE ANTHONY A. HEMPLO" at 4714.94,5022.96 h29.4 r270
  text "WRENN HARVYL F. TAJANTAJAN" at 4764.94,5017.8 h29.4 r270
  text "ENGR. VINCE JEBRYL G. MONTERO, ECE" at 4289.94,4707.47 h29.4 r270
  text "INSTRUCTOR:" at 4289.94,4387.16 h29.4 r270
  text "IN COLLABORATION WITH:" at 4764.94,4372.96 h29.4 r270
  text "JLCJLCJLCJLC" at 4489.94,3660.87 h29.4 r270
  text "VERSION 65ED8076" at 4539.94,3655.71 h29.4 r270
Mechanical Layer:
  circle w1 net "": c4800,5925 r43.31
  circle w1 net "": c4150,5925 r43.31
  circle w1 net "": c4825,3325 r43.31
  circle w1 net "": c4275,3325 r43.31
  lines w1 net "": 3637.5,6100 ccw(c3637.5,6125) 3662.5,6125 3662.5,6325 ccw(c3637.5,6325) 3637.5,6350 3662.5,6350 ccw(c3662.5,6325) 3637.5,6325 3637.5,6125 ccw(c3662.5,6125) 3662.5,6100 3637.5,6100
Mech15:
  circle w10 net "": c4800,5925 r65.87
  circle w10 net "": c4150,5925 r65.87
  circle w10 net "": c4825,3325 r65.87
  circle w10 net "": c4275,3325 r65.87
